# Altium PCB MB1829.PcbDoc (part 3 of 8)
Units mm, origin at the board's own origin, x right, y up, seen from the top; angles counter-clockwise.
Board outline 90 x 110 mm, 6 copper layers (Top Layer, Signal Layer 1, Signal Layer 2, Signal Layer 3, Signal Layer 4, Bottom Layer), stack 1.578 mm thick; 466 components, 354 nets, 2058 pads, 1522 vias.
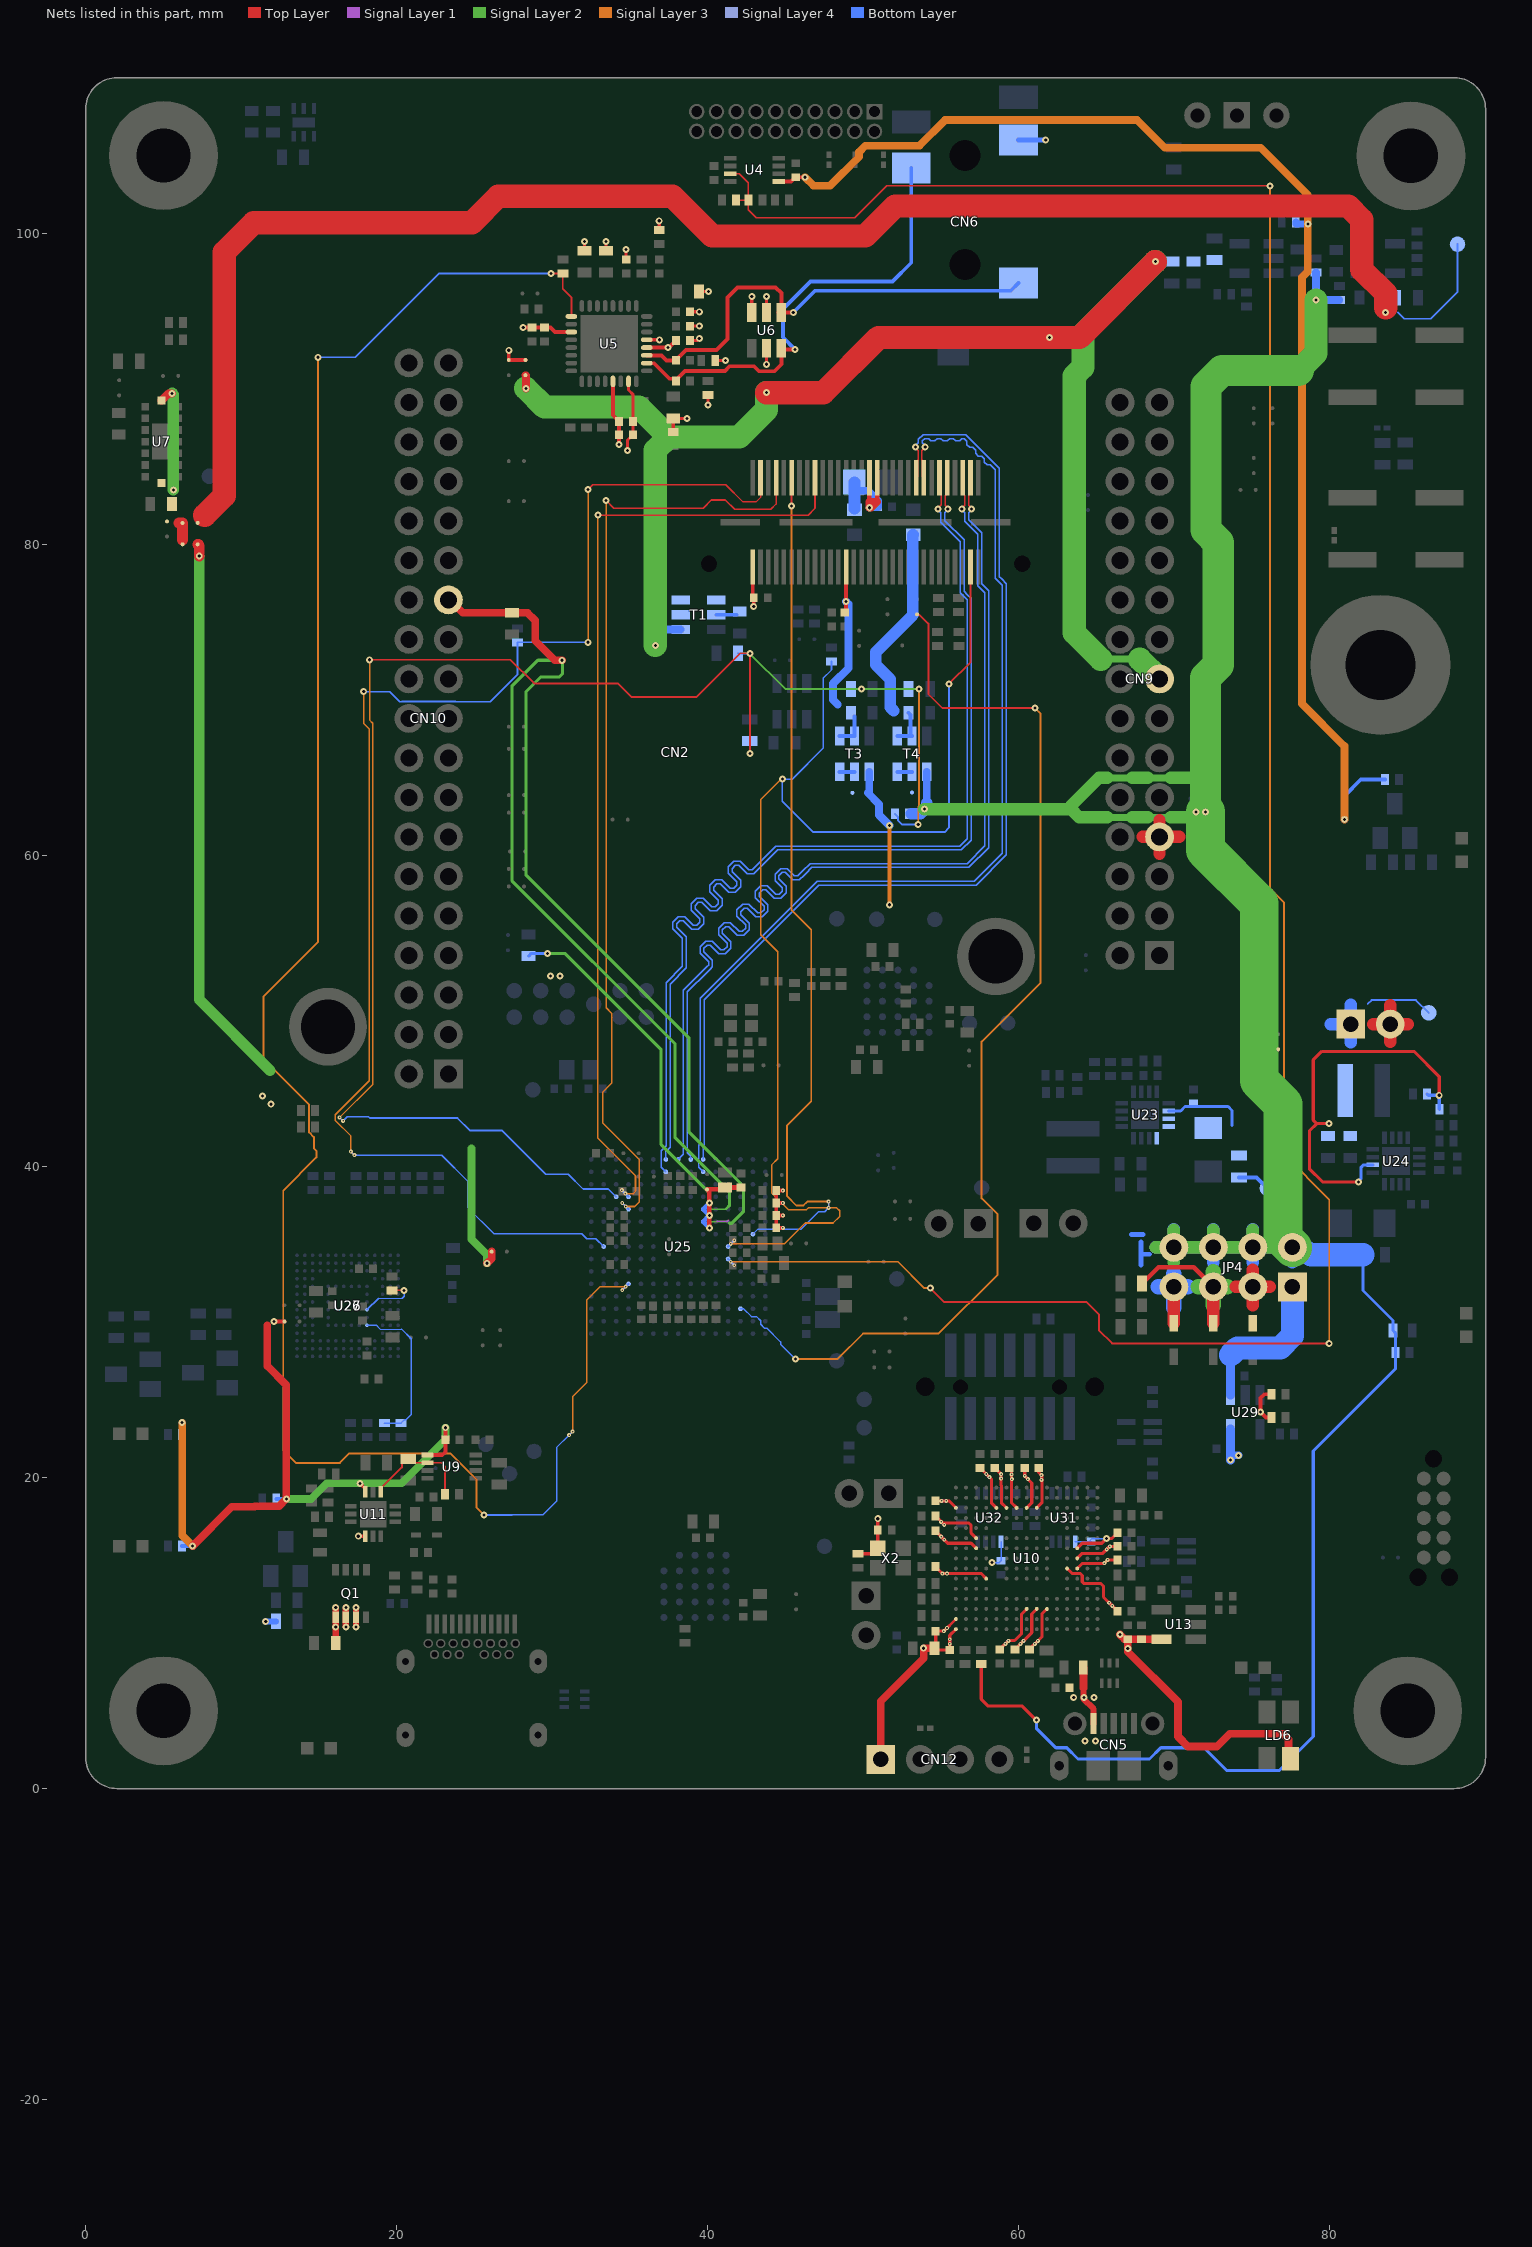
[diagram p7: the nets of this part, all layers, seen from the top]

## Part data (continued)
C119: library part MCD-00199, "Capacitor, Tantalum, 10uF, 16V, 3R, +/-10%, Type_A (3216 metric), T=1.6mm", Manufacturer=AVX, Manufacturer_Part_Number=TAJA106K016R, Package="3216 (metric)"
C121 C122 C123 C124: library part MCD-01101, "Capacitor, MLCC, 100pF, 50V, X7R, +/-5%, 0603, T=0.33mm", Manufacturer=AVX, Manufacturer_Part_Number=06035C101JAT4A, Package=0603
C126: library part MCD-02628, "Capacitor, MLCC, 3.3nF, 50V, X7R, +/-10%, 0402, T=0.5mm", Manufacturer=YAGEO, Manufacturer_Part_Number=CC0402KRX7R9BB332, Package=0402
C127 C128: library part MCD-01775, "Capacitor, MLCC, 3.3pF, 50V, NPO, +/-0.1pF, 0402, T=0.5mm", Manufacturer=YAGEO, Manufacturer_Part_Number=CC0402BRNPO9BN3R3, Package=0402
C129 C136: library part MCD-02610, "Capacitor, MLCC, 10uF, 25V, X5R, +/-10%, 1206, T=1.6mm", Manufacturer=YAGEO, Manufacturer_Part_Number=CC1206KKX5R8BB106, Package=1206
C131 C132 C133 C134: library part MCD-02607, "Capacitor, MLCC, 22uF, 10V, X5R, +/-20%, 0603, T=0.8mm", Manufacturer=YAGEO, Manufacturer_Part_Number=CC0603MRX5R6BB226, Package=0603
C147: library part MCD-00724, "Capacitor, MLCC, 470pF, 50V, NPO, +/-5%, 0402, T=0.5mm", Manufacturer=YAGEO, Manufacturer_Part_Number=CC0402JRNPO9BN471, Package=0402
C149: library part MCD-03051, "Capacitor, MLCC, 22nF, 50V, X7R, +/-10%, 0402, T=0.5mm", Manufacturer=YAGEO, Manufacturer_Part_Number=CC0402KRX7R9BB332, Package=0402
CN1: library part MCD-00147, "Socket, 10x2, 1.27mm, VR, TH, T=4.30mm/2.40mm", Manufacturer="AMPHENOL ICC", Manufacturer_Part_Number=20021311-00020T4LF
CN2: library part MCD-02128, "Socket, 30x2, 0.5mm, VR, SMD, T=3.05mm", Manufacturer=SAMTEC, Manufacturer_Part_Number=QSH-030-01-F-D-A
CN3: library part MCD-00031, "Header_Plug-of-nails, 5x2, 1.27mm, No legs", Manufacturer=TAG-CONNECTLLC, Manufacturer_Part_Number=TC2050-IDC-NL-FP
CN4: library part MCD-01108, "USB_TypeC, SMD+DIP, T= 2.96mm (for 1.6mm pcb)", Manufacturer="CHANT SINCERE (COXOC)", Manufacturer_Part_Number=317JD24BZTF3K3C3
CN5: library part MCD-00028, "MicroUSB_TypeB, 5pins, 0.65mm, RA, SMD, T=2.9mm", Manufacturer=MOLEX, Manufacturer_Part_Number=1050170001
CN6: library part MCD-00263, "Jack_ Socket-Stereo, 3.5mm, 4 pins, RA, SMD, T=5mm", Manufacturer=QIAOD, Manufacturer_Part_Number=PJ3028B-3_4P
CN9: library part MCD-02943, "Socket, 15x2, 2.54mm, VR, TH, T=8.51mm/2.64mm", Manufacturer=SAMTEC, Manufacturer_Part_Number=SSW-115-21-F-D
CN10: library part MCD-02944, "Socket, 19x2, 2.54mm, VR, TH, T=8.51mm/2.64mm", Manufacturer=SAMTEC, Manufacturer_Part_Number=SSW-119-21-F-D
CN11: library part MCD-02021, "Header_MIPI10, 5x2, 1.27mm, VR, SMD, T=6.1mm", Manufacturer=SAMTEC, Manufacturer_Part_Number=FTSH-105-01-L-DV-K-P-TR
CN12: library part MCD-00029, "Header, 4x1, 2.54mm, VR, TH, T=5.84mm/2.54mm", Manufacturer=SAMTEC, Manufacturer_Part_Number=TSW-104-07-G-S
D1 D2 D3: library part MCD-00034, Manufacturer=STMICROELECTRONICS, Manufacturer_HQ_COO=EU
D4: library part MCD-01677, "Small signal Schottky diodes", Manufacturer=STMICROELECTRONICS, Manufacturer_HQ_COO=EU, Manufacturer_Part_Number=BAT54KFILM, Package=SOD-523
H1 H2 H6 H7: library part MCD-02916, "Position hole,  C7D3R5 with 12mm M3 pillar on bottom", Manufacturer=N/A
H3: library part MCD-01612, "POSITION HOLE C9D4R5", Manufacturer=N/A
H4 H5: library part MCD-02915, "Position Hole C5D3R5: with no pillar in 3D, with pad design = c500h350m510.", Manufacturer=N/A
HW1: library part MCD-02189, "Sticker product 25x5 mm", Manufacturer=N/A
HW2: library part MCD-00234, "Sticker ES 6x6 mm", Manufacturer=N/A
HW3: library part MCD-00235, "Sticker Board 25x9 mm", Manufacturer=N/A
JP1 JP2 JP3: library part MCD-00683, "Header, 2x1, 2.54mm, VR, TH, T=5.84mm/2.54mm", Manufacturer=SAMTEC, Manufacturer_Part_Number=TSW-102-07-G-S
JP4: library part MCD-00686, "Header, 4x2, 2.54mm, VR, TH, T=5.84mm/2.54mm", Manufacturer=SAMTEC, Manufacturer_Part_Number=TSW-104-07-G-D
JP5: library part MCD-01904, "Header, 2x1, 2.54mm, VR, TH, T=5.84mm/2.54mm", Manufacturer=SAMTEC, Manufacturer_Part_Number=TSW-102-07-G-S
JP6: library part MCD-00045, "Header, 2x1, 2.54mm, VR, TH, T=5.84mm/2.54mm", Manufacturer=SAMTEC, Manufacturer_Part_Number=TSW-102-07-G-S
L1 L2: library part MCD-01986, "Ferrite bead, 470R @ 100MHz, +/-25%, 200mA, 0R6, 0402, T=0.55mm", Manufacturer=MURATA, Manufacturer_Part_Number=BLM15BD471SN1D, Package=0402
L3: library part MCD-00305, "Ferrite bead, 26R @ 100Mhz, +/-25%, 6000mA, 0R007, 0603, T=0.75mm", Manufacturer=MURATA, Manufacturer_Part_Number=BLM18KG260TN1, Package=0603
L4 L5: library part MCD-00047, "Ferrite bead, 600R @1 00MHz, +/-25%, 350mA, 0R5, 0603, T=0.8mm", Manufacturer=TAI-TECH, Manufacturer_Part_Number=FCM1608KF-601T03, Package=0603
L6: library part MCD-02582, "Inductor, 2.2uH, +/-20%, 8.9A, 0R022, 4x4mm, T=2.1mm", Manufacturer=COILCRAFT, Manufacturer_Part_Number=XGL4020-222MED
L7: library part MCD-02581, "Inductor, 3.3uH, +/-20%, 6.6A, 0R034, 4x4mm, T=2.1mm", Manufacturer=COILCRAFT, Manufacturer_Part_Number=XGL4020-332MED
L8: library part MCD-01060, "Inductor, 2.2uH, +/-20%, 0.7A, 0R156, 0805, T=0.9mm", Manufacturer=MURATA, Manufacturer_Part_Number=LQM21PN2R2MGH, Package=0805
LD1 LD2 LD3 LD7: library part MCD-00588, "LED Green, 0603 SMD, Forward Voltage Typ=2V, Max=2.5V", Manufacturer="OSRAM OPTO SEMICONDUCTORS", Manufacturer_Part_Number="LG Q396-PS-35", Package="LED 0603"
LD4 LD5: library part MCD-00586, "LED Red, 0603 SMD, Forward Voltage Typ=2V, Max=2.5V", Manufacturer="OSRAM OPTO SEMICONDUCTORS", Manufacturer_Part_Number="LS Q976-NR-1", Package="LED 0603"
LD6: library part MCD-02631, "LED Bicolor, Green/Red, 2V, 20mA,  4-PLCC", Manufacturer="WURTH ELEKTRONIK", Manufacturer_Part_Number=150141SV73110, Package=4-PLCC
Q1: library part MCD-01810, "N-channel 30 V, 6 mΩ typ, 11 A STripFET™ H6, Power MOSFET in a PowerFLAT™ 3.3x3.3 package", Manufacturer=STMICROELECTRONICS, Manufacturer_HQ_COO=EU, Package="PowerFLAT 3.3x3.3"
Q2 Q3 Q4 Q5: library part MCD-00073, "NPN Bipolar Transistor", Manufacturer="ON SEMICONDUCTOR", Manufacturer_Part_Number=BSR14, Package=SOT23
R1 R3 R5 R12 R20 R21 R25 R45 R48 R49 R52 R71 R72 R112 R113 R114 R115: library part MCD-00053, "Resistor, 10K, 0402, +/-1%, 1/16W", Manufacturer=YAGEO, Manufacturer_Part_Number=RC0402FR-0710KL, Package=0402
R2 R15 R16 R17 R18 R19 R22 R23 R24 R26 R27 R41 R57 R61 R63 R81 R85 R89 R93 R111 R121 R122: library part MCD-00052, "Resistor, 0R, 0402, +/-5%, 1/16W", Manufacturer=YAGEO, Manufacturer_Part_Number=RC0402JR-070RL, Package=0402
R4: library part MCD-00059, "Resistor, 100K, 0402, +/-1%, 1/16W", Manufacturer=YAGEO, Manufacturer_Part_Number=RC0402FR-0710KL, Package=0402
R6: library part MCD-00057, "Resistor, 2K2, 0402, +/-1%, 1/16W", Manufacturer=YAGEO, Manufacturer_Part_Number=RC0402FR-072K2L, Package=0402
R7 R8 R13 R14 R28 R29: library part MCD-00409, "Resistor, 1K8, 0402, +/-1%, 1/16W", Manufacturer=YAGEO, Manufacturer_Part_Number=RC0402FR-071K8L, Package=0402
R9 R56: library part MCD-00220, "Resistor, 10K, 0603, +/-1%, 1/10W", Alternate_Manufacturer=N/A, Manufacturer=YAGEO, Manufacturer_Part_Number=RC0603FR-0710KL, Package=0603
R10 R11: library part MCD-00485, "Resistor, 51R, 0402, +/-1%, 1/16W", Manufacturer=YAGEO, Manufacturer_Part_Number=RC0402FR-0751RL, Package=0402
R30 R95 R96 R97 R98 R99 R100 R101 R102: library part MCD-00063, "Resistor, 47K, 0402, +/-1%, 1/16W", Manufacturer=YAGEO, Manufacturer_Part_Number=RC0402FR-0747KL, Package=0402
R31: library part MCD-00458, "Resistor, 330K, 0603, +/-1%, 1/10W", Manufacturer=YAGEO, Manufacturer_Part_Number=RC0603FR-07330KL, Package=0603
R32: library part MCD-00444, "Resistor, 27K, 0603, +/-1%, 1/10W", Manufacturer=YAGEO, Manufacturer_Part_Number=RC0603FR-0727KL, Package=0603
R33 R86 R88 R119: library part MCD-00059, "Resistor, 100K, 0402, +/-1%, 1/16W", Manufacturer=YAGEO, Manufacturer_Part_Number=RC0402FR-07100KL, Package=0402
R34 R87 R130: library part MCD-00061, "Resistor, 1K, 0402, +/-1%,1/16W", Manufacturer=YAGEO, Manufacturer_Part_Number=RC0402FR-071KL, Package=0402
R35 R37 R79 R105 R107 R129: library part MCD-00222, "Resistor, 47K, 0603, 1%, 1/10W", Manufacturer=YAGEO, Manufacturer_Part_Number=RC0603FR-0747KL, Package=0603
R36 R55: library part MCD-00220, "Resistor, 10K, 0603, +/-1%, 1/10W", Manufacturer=YAGEO, Manufacturer_Part_Number=RC0603FR-0710KL, Package=0603
R38 R39: library part MCD-02455, "Resistor, 3K9, 0402, +/-1%, 1/16W, +/-100ppm/°C", Manufacturer=YAGEO, Manufacturer_Part_Number=RC0402FR-073K9L, Package=0402
R40 R43: library part MCD-00373, "Resistor, 1K2, 0402, +/-1%, 1/16W", Manufacturer=YAGEO, Manufacturer_Part_Number=RC0402FR-071K2L, Package=0402
R42 R44 R108 R123: library part MCD-00067, "Resistor, 100R, 0402, +/- 1%, 1/16W", Manufacturer=YAGEO, Manufacturer_Part_Number=RC0402FR-07100RL, Package=0402
R46: library part MCD-00185, "Resistor, 3K, 0402, +/-1%, 1/16W", Manufacturer=YAGEO, Manufacturer_Part_Number=RC0402FR-073KL, Package=0402
R47: library part MCD-00433, "Resistor, 2K4, 0402, +/-1%, 1/16W", Manufacturer=YAGEO, Manufacturer_Part_Number=RC0402FR-072K4L, Package=0402
R50 R51 R53: library part MCD-00065, "Resistor, 4K7, 0402, +/-1%, 1/16W", Manufacturer=YAGEO, Manufacturer_Part_Number=RC0402FR-074K7L, Package=0402
R54: library part MCD-00055, "Resistor, 2K7, 0402, +/-1%, 1/16W", Manufacturer=YAGEO, Manufacturer_Part_Number=RC0402FR-072K7L, Package=0402
R58 R64: library part MCD-00405, "Resistor, 160K, 0402, +/-1%, 1/16W", Manufacturer=YAGEO, Manufacturer_Part_Number=RC0402FR-07160KL, Package=0402
R59 R62 R66 R92 R103: library part MCD-00181, "Resistor, 0R, 0603, +/- 0.5mR, 1/4W", Manufacturer=ROHM, Manufacturer_Part_Number=PMR03EZPJ000, Package=0603
R60: library part MCD-00164, "Resistor, 220K, 0402, +/-1%, 1/16W", Manufacturer=YAGEO, Manufacturer_Part_Number=RC0402FR-07220KL, Package=0402
R65: library part MCD-00531, "Resistor, 82K, 0402, +/-1%, 1/16W", Manufacturer=YAGEO, Manufacturer_Part_Number=RC0402FR-0782KL, Package=0402
R67: library part MCD-00430, "Resistor, 22K, 0603, +/-1%, 1/10W", Manufacturer=YAGEO, Manufacturer_Part_Number=RC0603FR-0720KL, Package=0603
R68: library part MCD-00056, "Resistor, 0R, 0603, +/-5%, 1/10W", Manufacturer=YAGEO, Manufacturer_Part_Number=RC0603FR-07200RL, Package=0603
R69 R70: library part MCD-00184, "Resistor, 3K3, 0402, +/-1%, 1/16W", Manufacturer=YAGEO, Manufacturer_Part_Number=RC0402FR-073K3L, Package=0402
R73 R74 R75 R76: library part MCD-00056, "Resistor, 0R, 0603, +/-5%, 1/10W", Manufacturer=YAGEO, Manufacturer_Part_Number=RC0603JR-070RL, Package=0603
R77 R116 R120 R125: library part MCD-00441, "Resistor, 270R, 0402, +/-1%, 1/16W", Manufacturer=YAGEO, Manufacturer_Part_Number=RC0402FR-07270RL, Package=0402
R78: library part MCD-00495, "Resistor, 560K, 0402, +/-1%, 1/16W", Manufacturer=YAGEO, Manufacturer_Part_Number=RC0402FR-07100KL, Package=0402
R80 R104 R106: library part MCD-00223, "Resistor, 100K, 0603, +/- 1%, 1/10W", Manufacturer=YAGEO, Manufacturer_Part_Number=RC0603FR-07100KL, Package=0603
R82 R91: library part MCD-02570, "Resistor, 15K, 0402, +/-0.1%, 1/16W, +/-25ppm/°C", Manufacturer=YAGEO, Manufacturer_Part_Number=RT0402BRD0715KL, Package=0402
R83: library part MCD-02568, "Resistor, 6K8, 0402, +/-0.1%, 1/16W, +/-25ppm/°C", Manufacturer=YAGEO, Manufacturer_Part_Number=RT0402BRD076K8L, Package=0402
R84: library part MCD-02567, "Resistor, 12K, 0402, +/-0.1%, 1/16W, +/-25ppm/°C", Manufacturer=YAGEO, Manufacturer_Part_Number=RT0402BRD0712KL, Package=0402
R90: library part MCD-02550, "Resistor, 47K, 0402, +/-0.1%, 1/16W, +/-25ppm/°C", Manufacturer=YAGEO, Manufacturer_Part_Number=RT0402BRD0747KL, Package=0402
R109: library part MCD-00499, "Resistor, 620R, 0402, +/-1%, 1/16W", Manufacturer=YAGEO, Manufacturer_Part_Number=RC0402FR-07620RL, Package=0402
R110 R117 R118 R124 R126 R127: library part MCD-00481, "Resistor, 47R, 0402, +/-1%, 1/16W", Manufacturer=YAGEO, Manufacturer_Part_Number=RC0402FR-0747RL, Package=0402
R128: library part MCD-00430, "Resistor, 22K, 0603, +/-1%, 1/10W", Manufacturer=YAGEO, Manufacturer_Part_Number=RC0603FR-0722KL, Package=0603
R131: library part MCD-00062, "Resistor, 330R, 0402, +/-1%, 1/16W", Manufacturer=YAGEO, Manufacturer_Part_Number=RC0402FR-07330RL, Package=0402
SB1 SB2 SB3 SB10 SB11 SB12 SB13 SB14 SB15 SB16 SB17 SB18 SB19 SB22 SB25 SB28 SB34 SB35 SB38 SB39 SB40 SB43 SB46: library part MCD-02162, "Solder Bridge 0402 OFF", Manufacturer=YAGEO, Manufacturer_Part_Number=RC0402JR-070RL, Package=SB0402
SB4 SB5 SB6 SB9 SB20 SB21 SB23 SB24 SB26 SB27 SB29 SB30 SB31 SB32 SB33 SB36 SB37 SB41 SB42 SB44 SB45 SB47 SB48 SB49 SB50 SB51 SB52 SB53 SB54 SB55 SB56 SB57 SB58 SB59 SB60 SB61: library part MCD-01618, "Solder Bridge 0402 ON", Manufacturer=YAGEO, Manufacturer_Part_Number=RC0402JR-070RL, Package=SB0402
SB7 SB8: library part MCD-02162, "Solder Bridge 0402 OFF", Alternate_Manufacturer=N/A, Manufacturer=YAGEO, Manufacturer_Part_Number=RC0402JR-070RL, Package=SB0402
SW1: library part MCD-00566, "Mechanical Slide Switches 1K2 BLK ACT GOLD STRT MNT", Manufacturer=EAO, Manufacturer_Part_Number=09.03290.01
T1 T2 T3: library part MCD-01926, "20 V, P-channel Trench MOSFET", Manufacturer=NEXPERIA, Manufacturer_Part_Number=PMN30XPX, Package=TSOP6
T4: library part MCD-03170, "20 V, P-channel Trench MOSFET", Manufacturer=NEXPERIA, Manufacturer_Part_Number=PMN30XPX, Package=TSOP6
TP1 TP2 TP4 TP5 TP6 TP7 TP8 TP9 TP10 TP11 TP12 TP13 TP14 TP15 TP16 TP17 TP18 TP19 TP20 TP21 TP22 TP23 TP24 TP25 TP26 TP27 TP28 TP29 TP30 TP31: library part MCD-00074, "Test Point 1mm", Manufacturer=N/A
TP3: library part MCD-00074, "Test Point 1mm", Manufacturer=N/A, Manufacturer_Part_Number=n/a
U1 U2 U3 U8 U16 U17 U21: library part MCD-00170, "ESD protection 6V1", Manufacturer=STMICROELECTRONICS, Manufacturer_HQ_COO=EU, Manufacturer_Part_Number=ESDALC6V1-1U2
U4 U9 U31 U32: library part MCD-00264, "Dual bit dual supply bus transceiver", Manufacturer="TEXAS INSTRUMENTS"
U5: library part MCD-00265, "Low-Power, Stereo Codec with Headphone Amp", Manufacturer="CIRRUS LOGIC"
U6: library part MCD-00247, "Quad Bidir ESD protection", Manufacturer=STMICROELECTRONICS, Manufacturer_HQ_COO=EU
U7: library part MCD-02590, "Time-of-Flight 8x8 multizone ranging sensor with wide field of view", Manufacturer=STMICROELECTRONICS, Package="Optical LGA16"
U10: library part MCD-00596, "STM32F723IEK  (STM32F7) BGA176", Manufacturer=STMICROELECTRONICS, Manufacturer_HQ_COO=EU, Manufacturer_Part_Number=STM32F723IEK6
U11: library part MCD-01809, "USB Type-C Port Protection for USB Power Delivery, PPS compliant", Manufacturer=STMICROELECTRONICS, Manufacturer_HQ_COO=EU, Package=QFN-12L
U12: library part MCD-01207, "High power Transient voltage suppressor:25V/35A EOS and ESD transients protection.", Manufacturer=STMICROELECTRONICS, Manufacturer_HQ_COO=EU, Manufacturer_Part_Number=ESDA25P35-1U1M, Package=QFN1610
U13: library part MCD-00086, "Ultra low drop-low noise BiCMOS voltage, regulators low ESR capacitors compatible", Manufacturer=STMICROELECTRONICS, Manufacturer_HQ_COO=EU
U14 U35: library part MCD-00649, "Common mode filter with ESD protection for USB 2.0 interface", Manufacturer=STMICROELECTRONICS, Manufacturer_HQ_COO=EU
U15 U28: library part MCD-01026, "High power transient voltage suppressor", Manufacturer=STMICROELECTRONICS, Manufacturer_HQ_COO=EU, Manufacturer_Part_Number=ESDA7P120-1U1M, Package=QFN1610
U18: library part MCD-02159, "temperature sensor", Alternate_Manufacturer=N/A, Manufacturer=STMICROELECTRONICS, Manufacturer_HQ_COO=EU, Package="UDFN 6-pins 2x2x0.5mm"
U19 U20: library part MCD-02175, "LDO VOLTAGE REGULATOR, Adjustable, 150mA,", Manufacturer="TEXAS INSTRUMENTS", Manufacturer_Part_Number=TPS76301DBVT, Package=SOT23-5
U22: library part MCD-02166, "Memory,Octo-SPI-NOR,512Mb,x1/x8,133/200MHz,1.8V,DTR,BGA24, CMOS MXSMIO", Manufacturer=MACRONIX, Manufacturer_Part_Number=MX25UM51245GXDI00, Package=BGA24
U23 U24: library part MCD-02580, "Buck converter, 2A, 3V to 17V input, Fsw 1.25/2.5 MHz, 3x3 VQFN16", Manufacturer="TEXAS INSTRUMENTS"
U25: library part MCD-03270, "MCU, ARM Cortex-M33, 4MB Flash, 2.5MB RAM, With Crypto", Manufacturer=STMICROELECTRONICS, Manufacturer_HQ_COO=EU, Manufacturer_Part_Number=STM32U599NJH6Q, Package=TFBGA216
U26: library part MCD-01137, "4G MultiMediaCard (MMC) controller and NAND Flash", Manufacturer=MICRON, Package=FBGA153
U27: library part MCD-02799, "Memory, eMMC, 4GB, 15nm ,WFBGA , 153 pins", Manufacturer=KIOXIA, Manufacturer_Part_Number=THGBMTG5D1LBAIL, Package=WFBGA153
U29: library part MCD-00159, "500mA, Enhanced single channel power switches with active high enable pin", Manufacturer=STMICROELECTRONICS, Manufacturer_HQ_COO=EU
U30 U33: library part MCD-00136, "Dual Transil array for ESD protection", Manufacturer=STMICROELECTRONICS, Manufacturer_HQ_COO=EU
U34: library part MCD-02904, "Memory,Hexa-SPI-PSRAM,512Mb,x8x16,200MHz,1.8V,DDR,BGA24, PASR LVCMOS", Manufacturer="AP MEMORY TECHNOLOGY CORP.", Manufacturer_Part_Number=APS512XXN-OBR-BG, Package=BGA24
X1: library part MCD-01476, "Crystal, 16 MHz, 8pF, +/-20ppm, 200R, 2x1.6mm", Manufacturer=NDK, Manufacturer_Part_Number=NX2016SA-16MHZ-EXS00A-CS07826, Package=2x1.6mm
X2: library part MCD-00597, "Oscillator, SPXO, 25Mhz, +/-50ppm, 3V3, square wave, 2.5x2mm", Manufacturer=NDK, Manufacturer_Part_Number=NZ2520SH-25MHZ-END4869C, Package=2.5x2mm
X3: library part MCD-01479, "Crystal, 32.768kHz, 6pF, +/-20ppm, 80K, 2.05x1.2mm", Manufacturer=NDK, Manufacturer_Part_Number=NX2012SA-32.768KHZ-EXS00A-MU00527, Package=2.05x1.2mm

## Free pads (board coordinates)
  round 0.508 on Mech16: 1(22.966,-25.136) 1(71.839,-25.188)

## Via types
v1: diameter 0.45, hole 0.2, Top Layer to Bottom Layer, tented both sides, 1062 vias
v2: diameter 0.25, hole 0.1, Signal Layer 4 to Bottom Layer, tented both sides, 274 vias
v3: diameter 0.25, hole 0.1, Signal Layer 3 to Signal Layer 4, tented both sides, 119 vias
v4: diameter 0.25, hole 0.1, Top Layer to Signal Layer 1, tented both sides, 47 vias
v5: diameter 0.25, hole 0.1, Signal Layer 1 to Signal Layer 2, tented both sides, 20 vias

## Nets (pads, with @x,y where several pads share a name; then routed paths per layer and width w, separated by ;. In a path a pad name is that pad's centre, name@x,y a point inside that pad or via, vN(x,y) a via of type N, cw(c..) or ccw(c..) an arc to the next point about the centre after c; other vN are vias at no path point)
1V8: C117.2 CN9.15 R59.2 R62.2 SB2.1 SB49.1 T1.4 TP2.1 | length 98.2
  Top Layer w0.2: 62.475,93.3 62.5,93.325
  Top Layer w0.5: SB2.1@28.275,90.875 28.3,90.85 v1(28.3,90.025)
  Top Layer w1.5: v1(43.775,89.75) 47.425,89.75 50.975,93.3 v1(61.959,93.3) 62.475,93.3 63.9,93.3 v1(68.775,98.175)
  Signal Layer 2 w0.45: 65.725,72.614 67.775,72.614
  Signal Layer 2 w1.5: v1(28.3,90.025) 29.5,88.825 35.551,88.825 37.475,86.901 ; v1(36.625,73.5) 36.625,86.051 37.475,86.901 ; v1(43.775,89.75) 43.775,88.65 42.026,86.901 37.475,86.901 ; 65.257,72.616 63.55,74.324 63.55,90.825 64.115,91.39 64.115,93.515 v1(68.775,98.175) ; 67.775,72.625 67.775,72.609 CN9.15@69.04,71.344 CN9.15@68.973,71.411
  Bottom Layer w0.25: v1(61.959,93.3) TP2.1@63.394,93.3
  Bottom Layer w0.5: v1(36.625,73.5) SB49.1@36.625,74.521 T1.4@38.25,74.521
1V8_AUDIO: C11.2 C12.2 C13.2 C19.2 C20.2 SB2.2 SB3.2 U5.5 U5.12 U5.27 | length 11.2
  Top Layer w0.25: v1(27.2,92.475) SB3.2@27.2,91.85 SB2.2@28.275,91.85 ; v1(28.129,93.941) 28.141,93.941 28.15,93.95 C11.2@28.7,93.95 ; C11.2@28.7,93.95 C12.2@29.5,93.95 ; C12.2@29.5,93.941 29.885,93.941 30.175,93.65 U5.27@31.225,93.65 ; U5.5@33.9,90.475 33.9,88.3 C19.2@34.3,87.9 C20.2@34.3,87.05 v1(34.3,86.425) ; U5.12@36.075,92.65 37.5,92.65 C13.2@37.95,93.1
  other v1: 37.439,92.65
1V8_LCD: C22.2 C121.2 CN2.60 SB49.2 T1.1 T1.2 T1.5 T1.6 | length 3.6
  Top Layer w0.25: C22.2@42.885,76.636 CN2.60@42.885,78.357 ; v1(42.95,75.996) C22.2@42.95,76.571
  Bottom Layer w0.25: T1.2@40.55,75.471 C121.2@41.85,75.471
2V8: C118.2 R66.2 SB13.1 TP1.1 | length 108.3
  Top Layer w1.5: 7.65,81.875 8.9,83.125 8.9,98.77 10.805,100.675 24.835,100.675 26.535,102.375 37.725,102.375 40.275,99.825 50.125,99.825 52.05,101.75 81.171,101.75 82.05,100.871 82.05,97.656 83.575,96.131 83.575,95.2
  Bottom Layer w0.12: 84.382,94.9 84.782,94.5 86.475,94.5 88.2,96.225 TP1.1@88.2,99.3
  other v1: 83.571,94.9
3V3: C1.2 C71.2 CN9.7 JP1.2 R57.1 R77.2 R116.2 R120.2 R125.2 SB37.1 SB41.1 SB53.1 SB60.1 T3.4 U4.1 U9.1 U11.12 | length 193.8
  Top Layer w0.25: v1(12.1,30.025) SB41.1@12.775,30.025 ; v1(17.625,19.625) 17.975,19.275 U11.12@17.975,19.075 ; U9.1@21.975,21.45 22.925,21.45 23.125,21.65 C71.2@23.125,22.425 v1(23.125,23.2) ; U4.1@44.55,103.325 45.35,103.325 45.625,103.6 C1.2@45.65,103.6 v1(46.25,103.6)
  Top Layer w0.5: v1(6.875,15.6) 9.4,18.125 10.863,18.125 10.888,18.15 12.425,18.15 v1(12.9,18.625) 12.9,25.95 11.675,27.175 11.675,29.775 ; v1(25.8,33.775) 26.1,34.075 SB37.1@26.1,34.525
  Top Layer w0.7: SB60.1@7.2,80 7.25,80 7.25,79.925 7.3,79.875 v1(7.3,79.25)
  Top Layer w0.8: 67.95,61.184 CN9.7@69.04,61.184 ; 69.04,60.1 CN9.7@69.04,61.184 ; 69.04,62.275 CN9.7@69.04,61.184 ; 70.296,61.184 CN9.7@69.04,61.184 ; 82.775,49.15 JP1.2@83.87,49.15 ; 83.87,48.03 JP1.2@83.87,49.15 ; 83.87,50.366 JP1.2@83.87,49.15 ; 85,49.15 JP1.2@83.87,49.15
  Signal Layer 2 w0.5: v1(12.9,18.625) 14.5,18.625 15.5,19.625 v1(17.625,19.625) 20.325,19.625 23.125,22.425 v1(23.125,23.2) ; 24.8,41.15 24.8,35.325 25.8,34.325 v1(25.8,33.775)
  Signal Layer 2 w0.7: v1(7.3,79.25) 7.3,50.725 11.85,46.175
  Signal Layer 3 w0.25: v1(51.675,56.825) v1(51.675,61.925)
  Signal Layer 3 w0.5: v1(6.2,23.525) 6.2,16.275 v1(6.875,15.6) ; v1(46.25,103.6) 46.8,103.05 47.85,103.05 49.725,104.925 49.725,105.225 50.125,105.625 53.6,105.625 55.25,107.275 67.598,107.275 69.375,105.498 75.552,105.498 78.575,102.475 v1(78.575,100.6) 78.575,97.541 78.2,97.166 78.2,69.75 80.925,67.025 v1(80.925,62.3)
  Bottom Layer w0.25: R125.2@6.2,15.6 v1(6.875,15.6) ; R116.2@6.2,22.775 v1(6.2,23.525) ; R120.2@12.25,18.625 v1(12.9,18.625) ; v1(80.925,62.3) 80.925,63.825 81.979,64.879 R77.2@83.546,64.879
  Bottom Layer w0.45: R57.1@77.8,100.725 77.8,100.63 77.83,100.6 v1(78.575,100.6)
  Bottom Layer w0.5: T3.4@50.375,65.371 50.375,64.121 SB53.1@50.275,64.021 51.006,63.291 51.006,62.594 v1(51.675,61.925)
  other v1: 11.925,44 11.375,44.525 29.875,52.25 30.5,52.25
3V3_LCD: C24.2 C123.2 CN2.36 SB53.2 T3.1 T3.2 T3.5 T3.6 | length 13.4
  Top Layer w0.25: C24.2@48.8,75.621 48.885,75.706 v1(48.885,76.321) 48.885,78.536 CN2.36@48.889,78.54
  Bottom Layer w0.25: T3.6@48.475,65.371 T3.5@49.425,65.371 ; T3.1@48.475,67.671 T3.2@49.425,67.671 C123.2@49.425,68.946
  Bottom Layer w0.5: 48.35,69.7 48.05,70 48.05,71.046 49.05,72.046 49.05,76.156 v1(48.885,76.321)
3V3_SMPS: C131.1 C132.2 JP1.1 L6.2 R88.2 R89.2 TP13.1 U24.14 | length 33.4
  Top Layer w0.2: v1(79.929,42.752) 79.152,42.752 ; v1(81.825,39) 79.525,39 78.675,39.85 78.675,42.275 79.152,42.752 ; v1(87.025,44.575) 87.025,45.775 85.4,47.4 79.475,47.4 78.925,46.85 78.925,42.979 79.152,42.752
  Bottom Layer w0.12: 82.425,50.45 82.675,50.7 85.525,50.7 TP13.1@86.35,49.875
  Bottom Layer w0.2: v1(81.825,39) 81.825,39.067 82,39.242 82,39.95 82.15,40.1 U24.14@82.75,40.1 ; R88.2@86.25,44.65 86.325,44.575 v1(87.025,44.575) 87.025,43.7 R89.2@87.05,43.675
  Bottom Layer w0.8: 80.034,49.15 JP1.1@81.33,49.15 ; 81.33,47.97 JP1.1@81.33,49.15 ; 81.33,50.395 JP1.1@81.33,49.15
3V3_STLK: C73.1 C74.1 C75.1 C76.1 C77.1 C80.1 C83.1 C85.1 C86.1 C87.1 C89.1 C91.1 C92.1 C101.1 C102.2 C103.2 C104.1 C106.2 C107.1 C108.1 C109.1 C111.2 C145.2 C146.2 CN12.1 LD6.4 R45.1 U10.C1 U10.C5 U10.C6 U10.C7 U10.C8 U10.C9 U10.F3 U10.G3 U10.G13 U10.H13 U10.J12 U10.J13 U10.K4 U10.N8 U10.N9 U10.N10 U10.P1 U10.R1 U13.5 U31.1 U32.1 X2.4 | length 95.9
  Top Layer w0.2: C80.1@54.625,18.5 55.5,18.5 U10.C1@55.95,18.05 ; C92.1@54.65,14.25 v4(55.075,13.825) 57.575,13.825 U10.K4@57.9,13.5 ; C86.1@54.65,16.575 54.65,16.55 55.425,15.775 56.925,15.775 U10.G3@57.25,15.45 ; C83.1@54.65,17.525 v4@55,17.175 ; v4(55,17.15) v4@55,17.175 ; U10.R1@55.95,10.25 55.55,9.85 C111.2@55.55,8.9 54.7,8.9 C106.2@54.575,9.025 54.65,9.1 C104.1@54.65,10.125 v4(55.175,10.125) U10.P1@55.95,10.9 ; U10.F3@57.25,16.1 56.925,16.425 56.925,16.925 56.775,17.075 55.815,17.075 55.1,17.075 v4@55,17.175 ; C75.1@57.5,20.625 58.225,19.9 58.225,18.375 U10.C5@58.55,18.05 ; C76.1@58.45,20.625 v4(58.86,20.215) 58.86,19.5 58.875,19.485 58.875,18.375 ; C107.1@58.775,8.95 59.35,9.525 59.725,9.525 60.175,9.975 60.175,11.225 U10.N8@60.5,11.55 ; 59.013,18.238 58.875,18.375 ; U10.C6@59.2,18.05 58.875,18.375 ; C77.1@59.375,20.625 59.525,20.475 59.525,18.375 U10.C7@59.85,18.05 ; C108.1@59.75,8.95 60.825,10.025 60.825,11.225 U10.N9@61.15,11.55 ; C73.1@60.375,20.625 v4(60.375,20.1) 60.825,19.65 60.825,18.375 U10.C8@60.5,18.05 ; C109.1@60.675,8.95 61.475,9.75 61.475,11.225 U10.N10@61.8,11.55 ; U10.C9@61.15,18.05 61.475,18.375 61.475,20.125 v4(61.45,20.15) 61.275,20.325 C74.1@61.275,20.625 ; U10.J12@63.1,14.15 63.425,13.825 63.95,13.825 64.075,13.7 64.075,13.3 64.2,13.175 65.275,13.175 65.44,13.01 65.44,12.31 v4(66,11.75) C101.1@66.35,11.4 ; U10.J13@63.75,14.15 64.075,14.475 65.475,14.475 v4(65.7,14.7) C91.1@66.35,14.7 ; U10.H13@63.75,14.8 64.075,15.125 65.4,15.125 v4(65.85,15.575) C89.1@66.35,15.575 ; U10.G13@63.75,15.45 64.075,15.775 65.185,15.775 65.325,15.775 v1(65.625,16.075) 65.975,16.075 C87.1@66.35,16.45
  Top Layer w0.25: R45.1@49.65,15.1 50.575,15.1 X2.4@50.925,15.45 ; X2.4@50.925,15.45 C85.1@50.925,16.625 v1(50.925,17.35)
  Top Layer w0.5: CN12.1@51.115,1.875 51.115,5.615 53.875,8.375 v1(53.875,9.025) C106.2@54.575,9.025 ; v1(66.5,9.9) 66.795,9.605 66.995,9.605 C102.2@67,9.6 ; U13.5@69.175,9.6 C103.2@67.875,9.6 C102.2@67,9.6 ; LD6.4@77.45,1.925 77.332,2.043 77.332,3.175 76.977,3.53 73.555,3.53 72.725,2.7 70.871,2.7 70.225,3.346 70.225,5.575 67,8.8 v1(67,9) C102.2@67,9.6
  Signal Layer 1 w0.2: v4(55,16.2) v5(55.2,16) ; v4(55,17.15) v5(55.2,16.95) ; v4(55.025,18.5) v5(55.325,18.5) ; v4(55.075,13.825) v5(55.375,13.825) ; v4(55.175,10.125) v5(55.375,10.325) ; v4(55.55,9.3) v5(55.55,9.6) ; v4(57.9,20.225) v5(58.1,20.025) ; v5@58.86,19.935 v4(58.86,20.215) ; v4(59.125,9.3) v5(59.325,9.5) ; v5@59.525,19.925 v4(59.525,20.2) ; v4(60.1,9.3) v5(60.3,9.5) ; v4(60.375,20.1) v5(60.575,19.9) ; v4(61.025,9.3) v5(61.225,9.5) ; v5(61.45,19.85) v4(61.45,20.15) ; v5(65.5,14.5) v4(65.7,14.7) ; v5(65.65,15.375) v4(65.85,15.575) ; v5(65.8,11.95) v4(66,11.75)
  Bottom Layer w0.1: v1(58.275,14.525) 58.725,14.525 C146.2@58.85,14.65 U32.1@58.85,15.875 ; U31.1@63.625,15.875 C145.2@64.65,15.875 64.575,15.95 64.7,16.075 v1(65.625,16.075)
  other v5: 59.55,19.9 58.85,19.925
5V: JP4.2 JP4.4 JP4.6 JP4.8 R54.1 R61.1 R63.1 R78.2 R92.1 R103.1 R109.2 SB52.1 SB54.1 T4.4 TP23.1 U28.1 | length 205.1
  Top Layer w0.2: R54.1@57.575,8 57.575,5.75 58.025,5.3 60.225,5.3 v1(61.125,4.4)
  Top Layer w0.8: JP4.8@69.95,34.81 JP4.8@69.965,34.795
  Signal Layer 2 w0.4: v1@71.2,62.8 v1(71.375,62.8)
  Signal Layer 2 w0.45: 65.675,62.45 67.275,62.45 ; 65.675,64.99 67.275,64.99 ; 68.275,62.45 69.775,62.45 ; 68.275,64.99 69.775,64.99
  Signal Layer 2 w0.5: JP4.2@77.585,34.795 77.585,35.917
  Signal Layer 2 w0.8: v1(53.925,62.975) 63.35,62.975 ; 65.675,62.45 63.875,62.45 63.35,62.975 ; 65.675,64.99 65.15,64.99 63.35,63.19 63.35,62.975 ; 67.275,62.45 68.275,62.45 ; 67.275,64.99 68.275,64.99 ; 68.8,34.795 JP4.8@69.965,34.795 ; 69.775,62.45 71.025,62.45 v1(71.375,62.8) v1(72,62.8) ; 69.775,64.99 71.025,64.99 ; 69.965,33.825 JP4.8@69.965,34.795 ; 69.965,35.917 JP4.8@69.965,34.795 ; 72.505,35.917 JP4.6@72.505,34.795 ; 75.045,35.917 JP4.4@75.045,34.795 ; JP4.2@77.585,34.795 JP4.4@75.045,34.795 ; JP4.8@69.965,34.795 JP4.6@72.505,34.795 ; JP4.6@72.505,34.795 JP4.4@75.045,34.795
  Signal Layer 2 w1.5: 77.985,91.176 79.1,92.291 v1(79.1,95.7)
  Signal Layer 2 w2: v1(72,62.8) 72,71.425 72.819,72.244 72.819,80.111 72.019,80.912 72.019,90.142 73.053,91.176 77.985,91.176
  Signal Layer 2 w2.5: v1(72,62.8) 72,60.35 75.45,56.9 75.45,45.525 76.975,44 76.975,35.405 JP4.2@77.585,34.795
  Bottom Layer w0.2: v1(61.125,4.4) 61.125,3.877 62.377,2.625 63.075,2.625 63.8,1.9 68.4,1.9 69.125,2.625 71.9,2.625 73.35,1.175 76.75,1.175 78.925,3.35 78.925,21.7 84.2,26.975 R109.2@84.2,28.05 84.2,29.3 U28.1@84.05,29.45 84.05,30.1 82.125,32.025 R103.1@82.125,34.325
  Bottom Layer w0.25: R92.1@74.15,39.3 75.275,39.3 TP23.1@75.975,38.6
  Bottom Layer w0.3: 67.225,35.625 67.975,35.625 ; 67.85,33.65 67.85,34.35 ; 67.85,35.15 67.85,34.35 ; 68.4,34.35 67.85,34.35
  Bottom Layer w0.5: 54.075,63.371 T4.4@54.075,65.371 ; 78.785,34.325 78.855,34.255 ; R61.1@79.1,97.473 v1(79.1,95.7) R63.1@80.6,95.7
  Bottom Layer w0.75: R78.2@53.075,62.675 53.667,62.675 54.075,63.083 54.075,63.371
  Bottom Layer w0.8: 68.78,34.795 JP4.8@69.965,34.795 ; 69.965,35.98 JP4.8@69.965,34.795 ; 72.505,33.825 JP4.6@72.505,34.795 ; 72.505,35.98 JP4.6@72.505,34.795 ; 75.045,33.825 JP4.4@75.045,34.795 ; 75.045,35.98 JP4.4@75.045,34.795 ; 77.585,33.825 JP4.2@77.585,34.795 ; 77.585,35.98 JP4.2@77.585,34.795 ; 78.625,34.795 JP4.2@77.585,34.795 ; JP4.8@69.965,34.795 JP4.6@72.505,34.795 ; JP4.6@72.505,34.795 JP4.4@75.045,34.795 ; JP4.4@75.045,34.795 JP4.2@77.585,34.795
  Bottom Layer w1.5: 78.785,34.325 R103.1@82.125,34.325
5V_LCD: C122.2 L4.1 SB52.2 T4.1 T4.2 T4.5 T4.6 | length 16.3
  Bottom Layer w0.25: T4.6@52.175,65.371 T4.5@53.125,65.371 ; T4.1@52.175,67.671 T4.2@53.125,67.671 53.034,67.763 53.034,69.038 C122.2@52.9,69.171
  Bottom Layer w0.75: 51.948,69.298 51.725,69.521 51.725,71.328 50.8,72.253 50.8,73.071 53.175,75.446 53.175,80.6 L4.1@53.2,80.625
5V_STLK: C141.2 JP4.1 U29.1 | length 10.2
  Bottom Layer w0.6: U29.1@73.6,25.3 C141.2@73.6,26.525 73.6,27.875
  Bottom Layer w1.5: 73.6,27.875 74.05,28.325 76.8,28.325 77.585,29.11 JP4.1@77.585,32.255
5V_UCPD: C105.1 D1.1 JP4.5 Q1.1 Q1.2 Q1.3 R31.2 R129.1 U11.4 | length 17.8
  Top Layer w0.25: v1(17.525,16.225) U11.4@17.975,16.225 ; JP4.5@72.5,32.25 JP4.5@72.505,32.255
  Top Layer w0.3: R31.2@67.925,32.475 68.975,33.525 71.235,33.525 JP4.5@72.505,32.255
  Top Layer w0.4: C105.1@16.075,9.35 v1(16.075,10.4) Q1.1@16.075,11.025 v1(16.075,11.65) ; v1(16.725,10.4) Q1.2@16.725,11.025 v1(16.725,11.65) ; v1(17.375,10.4) Q1.3@17.375,11.025 v1(17.375,11.65)
  Top Layer w0.8: D1.1@72.5,29.92 JP4.5@72.5,32.25
  Signal Layer 2 w1: 71.525,32.255 JP4.5@72.505,32.255 ; 72.505,31.085 JP4.5@72.505,32.255 ; 72.505,33.225 JP4.5@72.505,32.255 ; JP4.5@73.405,32.255 JP4.5@72.505,32.255
  Bottom Layer w0.4: v1(11.575,10.75) R129.1@12.225,10.75
5V_USB_CHGR: C112.2 C142.2 CN5.1 D2.1 JP4.7 R33.2 R34.2 U15.1 U29.5 | length 15.4
  Top Layer w0.25: R34.2@76.25,23.85 75.875,23.85 v1(75.525,24.2) 75.525,25.1 75.775,25.35 R33.2@76.25,25.35
  Top Layer w0.4: 64.15,6.475 64.15,5.775 64.8,5.125 CN5.1@64.8,4.175
  Top Layer w0.5: 64.15,6.475 U15.1@64.15,7.775
  Top Layer w0.8: D2.1@69.95,29.92 JP4.7@69.95,32.24
  Top Layer w1: JP4.7@69.95,32.24 JP4.7@69.965,32.255
  Bottom Layer w0.5: 73.6,21.435 73.61,21.425 v1(74.125,21.425)
  Bottom Layer w0.6: v1(73.6,21.125) 73.6,21.435 C142.2@73.6,21.85 U29.5@73.6,23.1
  Bottom Layer w1: 68.95,32.255 JP4.7@69.965,32.255 ; 69.965,30.925 JP4.7@69.965,32.255 ; JP4.7@69.965,33.1 JP4.7@69.965,32.255 ; JP4.7@70.85,32.255 JP4.7@69.965,32.255
  other v1: 64.255,3.06 64.93,3.06 63.525,5.85 64.175,5.85 64.825,5.85
5V_VIN: D3.1 JP4.3 SB26.1 | length 4.5
  Top Layer w0.8: 73.95,32.255 JP4.3@75.045,32.255 ; 75.045,31.075 JP4.3@75.045,32.255 ; 75.045,33.35 JP4.3@75.045,32.255 ; 76.14,32.255 JP4.3@75.045,32.255
5VIN: C129.2 C130.2 R92.2 U23.10 U23.11 U23.12 U23.13 | length 5.3
  Bottom Layer w0.2: U23.10@69.622,43.564 70.394,43.564 70.68,43.85 73.45,43.85 73.7,43.6 73.7,42.625
A_GND: C3.1 C4.1 C5.1 C7.1 C9.1 C10.1 C13.1 C16.1 C19.1 C20.1 CN6.3 R4.1 R10.1 R11.1 R15.1 U5.7 U5.13 U6.2 U6.3 U6.5 | length 18.3
  Top Layer w0.2: C3.1@32.075,98.875 v1(32.075,99.475) ; C4.1@33.45,98.875 v1(33.45,99.475) ; C5.1@34.75,98.4 v1(34.75,98.95) ; v1(34.825,86.025) 34.825,86.675 C20.1@35.2,87.05 C19.1@35.2,87.9 35.2,89.625 34.9,89.925 U5.7@34.9,90.475 ; U5.13@36.075,93.15 v1(36.9,93.15) ; R4.1@36.875,100.2 v1(36.875,100.8) ; R15.1@37.775,87.225 C16.1@37.775,88.1 v1(38.65,88.1) ; C13.1@38.85,93.1 39.25,93.1 39.333,93.1 39.45,93.217 v1(39.45,93.239) ; C10.1@38.85,94.025 v1(39.45,94.025) ; C9.1@38.85,94.95 v1(39.45,94.95) ; C7.1@39.425,96.25 v1(40.05,96.25) ; v1(40,88.95) R11.1@40,89.6 ; R10.1@40.475,91.825 40.525,91.775 40.575,91.825 v1(41.125,91.825) ; U6.3@42.825,94.9 v1(42.825,95.925) ; v1(43.775,91.575) U6.5@43.775,92.6 ; U6.2@43.775,94.9 v1(43.775,95.925)
  Bottom Layer w0.3: CN6.3@59.975,106 v1(61.725,106)
AGND: C25.1 C37.2 C41.1 C43.1 C45.1 C48.1 C125.1 CN10.25 L1.2 SB30.2 U25.K5 U25.K6 | length 135.5
  Top Layer w0.25: v4(44.825,36.05) C48.1@44.4,36.05 C45.1@44.4,36.85 ; v4(44.825,36.85) C45.1@44.4,36.85 ; v4(44.825,37.65) C43.1@44.4,37.65 ; v4(44.825,38.45) C41.1@44.4,38.45 C43.1@44.4,37.65 ; C45.1@44.4,36.85 C43.1@44.4,37.65
  Top Layer w0.3: v1(40.1,36.05) v1(40.1,36.85) v1(40.1,37.65) 40.1,38.375 SB30.2@39.95,38.525 40.975,38.525 L1.2@41.1,38.65 C37.2@42.125,38.65
  Top Layer w0.5: CN10.25@23.32,76.424 23.412,76.424 24.237,75.6 C25.1@27.4,75.6 28.4,75.6 28.9,75.1 28.9,73.8 30.155,72.545 v1(30.625,72.545)
  Signal Layer 1 w0.1: 40.575,36.475 41.275,36.475 41.325,36.525
  Signal Layer 2 w0.1: 40.1,36.45 41.3,36.45 41.4,36.35 ; 40.1,37.25 41.15,37.25 41.2,37.3
  Signal Layer 2 w0.2: v1(29.7,53.7) 30.8,53.7 37,47.5 37,41.4 40.1,38.3 v1(40.1,37.65) 40.1,37.25 v1(40.1,36.85) 40.1,36.45 v1(40.1,36.05) ; 41.2,37.3 41.4,37.5 41.4,38.336 37.9,41.836 37.9,47.873 27.4,58.373 27.4,70.875 29.07,72.545 v1(30.625,72.545) 30.67,72.545 30.65,72.525 30.65,71.66 30.465,71.475 29.273,71.475 28.3,70.502 28.3,58.746 38.8,48.246 38.8,42.209 42.3,38.709 42.3,37.114 41.536,36.35 41.4,36.35
  Bottom Layer w0.2: C125.1@28.475,53.525 28.65,53.7 v1(29.7,53.7)
  Bottom Layer w0.3: v1(40.1,36.05) U25.K6@39.7,36.45 v1(40.1,36.85) U25.K5@39.7,37.25 v1(40.1,37.65)
AOUTA: C14.2 CN6.6 U5.11 U6.1 | length 29.8
  Top Layer w0.25: U5.11@36.075,92.15 37.025,92.15 37.35,91.825 C14.2@37.95,91.825 37.95,91.85 38.08,91.98 38.6,92.5 40.55,92.5 41.253,93.203 41.253,95.878 41.896,96.521 44.354,96.521 44.725,96.15 44.725,95.07 U6.1@44.55,94.895 ; U6.1@44.725,94.9 v1(45.492,94.9)
  Bottom Layer w0.25: v1(45.492,94.9) 46.892,96.3 59.475,96.3 CN6.6@59.975,96.8
AOUTB: C15.2 CN6.4 U5.10 U6.6 | length 30.3
  Top Layer w0.25: U5.10@36.075,91.65 36.084,91.641 36.534,91.641 37.53,90.645 37.82,90.645 37.95,90.515 C15.2@37.95,90.5 38.08,90.63 38.08,90.705 38.525,91.15 41.1,91.15 41.4,91.45 42.975,91.45 43.3,91.125 44.275,91.125 44.725,91.575 U6.6@44.725,92.6 44.8,92.525 v1(45.61,92.525)
  Bottom Layer w0.25: v1(45.61,92.525) 44.825,93.31 44.825,95.121 46.604,96.9 51.875,96.9 53.075,98.1 CN6.4@53.075,104.2
Audio_MEMs_LED: R1.2 R2.1 U4.7 U25.M9 | length 156.7
  Top Layer w0.12: U4.7@41.45,103.825 42.025,103.825 42.6,103.25 R2.1@42.6,102.125 ; R1.2@41.8,102.125 R2.1@42.6,102.125 ; v1(54.3,32.175) 55.2,31.275 64.349,31.275 65.14,30.484 65.14,29.469 65.986,28.622 v1(79.953,28.622) ; v1(76.149,103.049) v1(76.149,103.049) v1(76.149,103.049) 51.5,103.05 49.45,101 43.1,101 42.6,101.5 R2.1@42.6,102.125
  Signal Layer 3 w0.12: v3(41.475,33.875) 46.6,33.875 52.225,33.875 53.925,32.175 v1(54.3,32.175) ; v1(76.149,103.049) 76.15,57.85 77.05,56.95 77.05,40.775 79.953,37.872 v1(79.953,28.622)
  Signal Layer 4 w0.1: v3(41.475,33.875) v2(41.7,33.65)
  Bottom Layer w0.12: U25.M9@41.3,34.05 v2(41.7,33.65)
Audio_RSTn: R5.2 U5.25 U25.D11 | length 133.7
  Top Layer w0.12: v1(29.925,97.4) R5.2@30.675,97.4 30.675,96.425 31.225,95.875 U5.25@31.225,94.65
  Signal Layer 3 w0.1: v3(31.3,22.95) 31.3,25.192 32.203,26.095 32.203,31.392 33.086,32.275 v3(34.725,32.275)
  Signal Layer 3 w0.12: v1(14.925,92.025) 14.925,54.428 11.44,50.943 11.44,46.882 14.368,43.954 14.368,42.188 14.67,41.886 14.67,41.175 14.835,41.01 14.835,40.585 12.7,38.45 12.7,21.75 13.51,20.94 16.34,20.94 16.95,21.55 23.45,21.55 25.12,19.88 25.12,18.08 v1(25.6,17.6)
  Signal Layer 4 w0.1: v2(31.075,22.725) v3(31.3,22.95) ; v2(34.5,32.05) v3(34.725,32.275)
  Bottom Layer w0.1: 27.425,17.6 29.4,17.6 30.275,18.475 30.275,21.925 v2(31.075,22.725)
  Bottom Layer w0.12: v1(14.925,92.025) 17.325,92.025 22.7,97.4 v1(29.925,97.4) ; v1(25.6,17.6) 27.425,17.6 ; v2(34.5,32.05) U25.D11@34.9,32.45
AVDD_TOF_SENSOR: C21.2 SB12.2 SB13.2 SB60.2 U7.B1 U7.B7 | length 8.4
  Top Layer w0.5: U7.B7@4.875,89.25 5.325,89.7 v1(5.555,89.7)
  Top Layer w0.7: 6,81.375 SB13.2@6.2,81.375 ; 6.225,80.275 SB13.2@6.225,81.375
  Signal Layer 2 w0.75: v1(5.555,89.7) 5.636,89.618 v1(5.636,83.5)
BLGND: C119.2 C120.1 CN2.27 CN2.29 L5.2 | length 8.8
  Top Layer w0.3: 50.385,82.738 CN2.29@50.385,84.097 ; 50.885,82.738 CN2.27@50.885,84.097
  Top Layer w0.5: v1@50.385,82.359 v1(50.391,82.353) 50.5,82.353 50.885,82.738 50.385,82.738 v1@50.385,82.359
  Bottom Layer w0.5: C119.2@49.425,83.525 49.504,83.446 50.304,83.446 50.945,82.805 50.945,82.426 C120.1@50.95,82.421 50.95,82.396 50.945,82.391 50.43,82.391 v1(50.391,82.353)
  Bottom Layer w0.75: L5.2@49.425,82.296 49.425,83.525 C119.2@49.425,83.996
DBn: R35.2 R41.2 U9.2 U11.10 | length 7.2
  Top Layer w0.12: U11.10@18.975,19.075 18.975,19.3 20.325,20.65 20.325,20.94 20.585,21.2 R35.2@20.725,21.2 ; R35.2@20.725,20.95 U9.2@21.975,20.95 22.85,20.95 23.1,20.7 R41.2@23.1,18.925
DS: R30.2 U26.H5 U27.H5 | length 3.9
  Top Layer w0.09: R30.2@19.7,32.025 v1(20.475,32.025)
  Bottom Layer w0.08: 18.835,31.536 20.361,31.536
  Bottom Layer w0.09: U27.H5@18.085,30.786 18.835,31.536 ; 20.361,31.536 20.475,31.65 v1(20.475,32.025)
DSI.CK_N: CN2.3 U25.J1 | length 66.8
  Top Layer w0.09: CN2.3@56.763,83.15 56.763,82.597 56.762,82.508 56.95,82.32 v1(56.95,82.275)
  Bottom Layer w0.09: U25.J1@38.9,40.45 38.9,40.645 38.675,40.87 38.675,51.22 39.978,52.523 40.14,52.685 40.297,52.842 40.297,53.258 39.747,53.807 39.747,54.016 39.956,54.224 40.164,54.224 40.714,53.675 41.13,53.675 41.485,54.03 41.485,54.446 40.935,54.995 40.935,55.204 41.144,55.412 41.352,55.412 41.902,54.863 42.317,54.863 42.673,55.218 42.673,55.634 42.123,56.183 42.123,56.392 42.332,56.6 42.54,56.6 43.09,56.051 43.505,56.051 43.86,56.406 43.86,56.821 43.311,57.371 43.311,57.58 43.52,57.788 43.728,57.788 44.278,57.239 44.693,57.239 45.048,57.594 45.048,58.009 44.575,58.483 44.575,58.692 44.783,58.9 44.992,58.9 45.466,58.427 45.881,58.427 46.185,58.73 46.288,58.833 46.676,59.221 56.776,59.221 58.055,60.5 58.055,77 57.603,77.452 57.603,80.747 56.762,81.588 56.762,82.042 56.95,82.23 v1(56.95,82.275)
DSI.CK_P: CN2.5 U25.H1 | length 66.9
  Top Layer w0.09: v1(56.325,82.275) 56.325,82.32 56.512,82.508 56.512,82.7 CN2.5@56.513,83.15
  Bottom Layer w0.09: U25.H1@38.1,40.45 38.425,40.775 38.425,51.324 39.801,52.7 39.963,52.862 40.047,52.946 40.047,53.154 39.497,53.704 39.497,54.119 39.852,54.474 40.268,54.474 40.817,53.925 41.026,53.925 41.235,54.133 41.235,54.342 40.685,54.892 40.685,55.307 41.04,55.662 41.456,55.662 42.005,55.113 42.214,55.113 42.423,55.321 42.423,55.53 41.873,56.08 41.873,56.495 42.228,56.85 42.644,56.85 43.193,56.301 43.402,56.301 43.61,56.509 43.61,56.718 43.061,57.267 43.061,57.683 43.416,58.038 43.832,58.038 44.381,57.489 44.59,57.489 44.798,57.697 44.798,57.906 44.325,58.379 44.325,58.795 44.68,59.15 45.095,59.15 45.569,58.677 45.778,58.677 46.008,58.907 46.111,59.01 46.573,59.471 56.673,59.471 57.805,60.604 57.805,76.896 57.353,77.348 57.353,80.643 56.512,81.484 56.512,82.042 56.325,82.23 v1(56.325,82.275)
DSI.D0_N: CN2.11 U25.G2 | length 68.5
  Top Layer w0.09: v1(54.8,82.275) 54.8,82.32 55.014,82.534 55.014,83.137 54.994,83.157 54.994,84.175 CN2.11@54.889,84.28
  Bottom Layer w0.09: U25.G2@37.3,39.65 37.005,39.945 37.005,41.005 37.325,41.325 37.325,51.822 38.367,52.864 38.367,54.283 38.367,54.659 37.749,55.277 37.749,55.693 38.104,56.048 38.52,56.048 39.069,55.498 39.278,55.498 39.486,55.707 39.486,55.915 38.937,56.465 38.937,56.88 39.292,57.236 39.708,57.236 40.257,56.686 40.466,56.686 40.674,56.895 40.674,57.103 40.125,57.653 40.125,58.068 40.48,58.423 40.896,58.423 41.445,57.874 41.654,57.874 41.862,58.083 41.862,58.291 41.313,58.841 41.313,59.256 41.668,59.611 42.083,59.611 42.633,59.062 42.842,59.062 43.525,59.745 44.381,60.601 56.205,60.601 56.675,61.072 56.675,76.428 56.223,76.88 56.223,80.175 54.988,81.411 54.988,82.042 54.8,82.23 v1(54.8,82.275)
DSI.D0_P: CN2.9 U25.G1 | length 67.5
  Top Layer w0.09: CN2.9@55.389,84.28 55.284,84.175 55.284,83.157 55.264,83.137 55.264,82.519 55.425,82.358 v1(55.425,82.275)
  Bottom Layer w0.09: U25.G1@37.3,40.45 37.3,40.946 37.575,41.221 37.575,51.718 38.617,52.761 38.617,54.033 38.617,54.762 37.999,55.38 37.999,55.589 38.208,55.798 38.416,55.798 38.966,55.248 39.381,55.248 39.736,55.603 39.736,56.019 39.187,56.568 39.187,56.777 39.395,56.986 39.604,56.986 40.154,56.436 40.569,56.436 40.924,56.791 40.924,57.207 40.375,57.756 40.375,57.965 40.583,58.173 40.792,58.173 41.342,57.624 41.757,57.624 42.112,57.979 42.112,58.395 41.563,58.944 41.563,59.153 41.771,59.361 41.98,59.361 42.529,58.812 42.945,58.812 43.701,59.568 44.485,60.351 56.308,60.351 56.925,60.968 56.925,76.532 56.686,76.77 56.473,76.984 56.473,80.279 55.238,81.514 55.238,82.042 55.425,82.23 v1(55.425,82.275)
DSI.D1_N: CN2.17 U25.K1 | length 67.5
  Top Layer w0.09: v1(53.35,86.25) 53.35,86.181 53.514,86.017 53.514,85.55 53.514,85.423 53.494,85.403 53.494,84.385 CN2.17@53.389,84.28
  Bottom Layer w0.09: U25.K1@39.7,40.45 39.7,41.325 39.775,41.4 39.775,50.722 47.144,58.091 57.244,58.091 59.185,60.032 59.185,77.468 58.88,77.772 58.733,77.92 58.733,84.896 56.579,87.05 53.834,87.05 53.538,86.754 53.538,86.535 53.35,86.347 v1(53.35,86.25)
DSI.D1_P: CN2.15 U25.K2 | length 68.4
  Top Layer w0.09: CN2.15@53.889,84.28 53.784,84.385 53.784,85.403 53.764,85.423 53.764,85.654 53.764,86.014 53.975,86.225 v1(53.975,86.25)
  Bottom Layer w0.09: U25.K2@39.7,39.65 39.4,39.95 39.4,41.379 39.525,41.504 39.525,50.826 47.041,58.341 57.141,58.341 58.935,60.136 58.935,77.364 58.792,77.507 58.615,77.684 58.483,77.816 58.483,84.792 58.172,85.103 57.96,85.103 57.783,85.28 57.783,85.492 57.606,85.669 57.394,85.669 57.217,85.846 57.217,86.058 57.041,86.234 56.829,86.234 56.652,86.411 56.652,86.623 56.475,86.8 56.338,86.8 56.188,86.65 55.938,86.65 55.788,86.8 55.538,86.8 55.388,86.65 55.138,86.65 54.988,86.8 54.738,86.8 54.588,86.65 54.338,86.65 54.188,86.8 53.938,86.8 53.787,86.65 53.787,86.535 53.975,86.347 v1(53.975,86.25)
DSI_BL_CTRL: CN2.53 U25.D5 | length 61.8
  Top Layer w0.1: v1(33.461,82.814) 33.95,82.325 39.7,82.325 40.225,82.85 41.126,82.85 41.726,82.25 44.05,82.25 44.389,82.589 CN2.53@44.389,84.28
  Signal Layer 3 w0.1: v1(33.461,82.814) 33.461,50.205 33.825,49.841 33.825,45.372 33.253,44.8 33.253,42.772 35.6,40.425 35.6,37.725 35.3,37.425 v3(34.725,37.425)
  Signal Layer 4 w0.1: v2(34.5,37.65) v3(34.725,37.425)
  Bottom Layer w0.12: v2(34.5,37.65) U25.D5@34.9,37.25
DSI_PWR_ON: R73.1 R74.1 R75.1 R76.1 R78.1 U25.C4 | length 108.8
  Top Layer w0.12: v1(18.25,72.575) 18.254,72.579 27.31,72.579 28.834,71.055 34.22,71.055 35.1,70.175 39.265,70.175 42.087,72.996 42.679,72.996 v1(42.7,72.975) v1(42.7,66.55)
  Signal Layer 2 w0.12: v1(42.7,72.975) 44.975,70.7 v1(49.875,70.7) v1(53.575,70.7)
  Signal Layer 3 w0.1: v3(16.325,43.15) 18.45,45.275 18.45,68.5 18.25,68.7 18.25,71.053 v1(18.25,72.575)
  Signal Layer 3 w0.12: v1(53.525,61.975) 53.525,63.119 53.575,63.169 v1(53.575,70.7)
  Signal Layer 4 w0.1: v3(16.325,43.15) v2(16.55,42.925)
  Bottom Layer w0.1: 27.425,41.65 29.575,39.5 31.025,39.5 31.975,38.55 33.6,38.55 U25.C4@34.1,38.05
  Bottom Layer w0.12: v2(16.55,42.925) 16.82,43.195 18.183,43.195 18.263,43.115 23.899,43.115 24.694,42.32 26.755,42.32 27.425,41.65 ; R73.1@41.95,72.996 41.971,72.975 v1(42.7,72.975) ; v1(42.7,66.55) R76.1@42.7,67.346 ; R75.1@49.2,70.696 v1@49.821,70.696 ; R78.1@52.025,62.675 52.22,62.48 52.22,62.252 52.497,61.975 v1(53.525,61.975) ; R74.1@52.9,70.696 v1@53.521,70.696
DSI_RESETn: CN2.57 R71.2 U25.B8 | length 91.2
  Top Layer w0.1: v1(32.3,83.525) 32.6,83.825 41.158,83.825 42.258,82.725 43.1,82.725 43.389,83.014 CN2.57@43.389,84.28
  Signal Layer 3 w0.1: v3(17.05,40.95) 17.05,41.95 16.05,42.95 16.05,43.325 18.229,45.504 18.229,68.121 17.875,68.475 v1(17.875,70.525) ; v1(32.3,73.7) v1(32.3,83.525)
  Signal Layer 4 w0.1: v3(17.05,40.95) v2(17.275,40.725)
  Bottom Layer w0.1: v2(17.275,40.725) 22.895,40.725 24.58,39.04 24.58,37.335 26.245,35.67 31.892,35.67 32.212,35.35 32.8,35.35 U25.B8@33.3,34.85
  Bottom Layer w0.12: v1(17.875,70.525) 17.876,70.524 19.554,70.524 20.199,69.879 20.321,69.879 20.331,69.889 23.769,69.889 23.779,69.879 26.01,69.879 27.75,71.619 R71.2@27.75,73.7 v1(32.3,73.7)
DSI_SPI_USART_CS: SB15.2 U25.N13 | length 71.6
  Top Layer w0.12: SB15.2@53.45,75.496 53.476,75.471 53.604,75.471 54.175,74.9 54.175,70.375 55.075,69.475 v1(61.028,69.475) v1@61.05,69.475
  Signal Layer 3 w0.12: v1(45.625,27.625) 48.35,27.625 49.975,29.25 54.825,29.25 58.625,33.05 58.625,36.925 57.6,37.95 57.6,48.025 61.399,51.824 61.399,69.104 v1(61.028,69.475)
  Bottom Layer w0.1: U25.N13@42.1,30.85 42.3,30.85 42.8,30.35 43.125,30.35 43.4,30.075 43.4,29.85 43.65,29.6 43.8,29.6 44.679,28.721 44.679,28.571 v1(45.625,27.625)
DSI_SWIRE: CN2.43 U25.D4 | length 62.2
  Top Layer w0.1: v1(32.925,81.875) 46.45,81.875 46.889,82.314 CN2.43@46.889,84.28
  Signal Layer 3 w0.1: v1(32.925,81.875) 32.925,41.828 35.35,39.402 35.35,38.4 35.2,38.25 v3(34.7,38.25)
  Signal Layer 4 w0.1: v2(34.475,38.475) v3(34.7,38.25)
  Bottom Layer w0.12: v2(34.475,38.475) U25.D4@34.9,38.05
DSI_TE: CN2.49 U25.P7 | length 56.3
  Top Layer w0.12: v1(45.389,82.464) CN2.49@45.389,84.28
  Signal Layer 3 w0.12: v1(45.389,82.464) 45.389,56.486 46.65,55.225 46.65,44.2 45.1,42.65 45.1,39.625 45.1,38.088 45.698,37.49 46.14,37.49 46.388,37.738 v3(47.763,37.738)
  Signal Layer 4 w0.1: v2(47.763,37.338) v3(47.763,37.738)
  Bottom Layer w0.1: U25.P7@42.9,35.65 43.2,35.95 45.975,35.95 47.11,37.085 47.51,37.085 v2(47.763,37.338)
DSI_TOUCH_INT: CN2.4 R72.1 U25.M8 | length 81.4
  Top Layer w0.12: v1(55.5,71.025) 56.889,72.414 CN2.4@56.889,78.54
  Signal Layer 3 w0.1: v3(41.475,35.025) 44.925,35.025 46.263,36.363 48.055,36.363 48.475,36.784 48.475,37.15 48.275,37.35 46.475,37.35 46.35,37.225 45.175,37.225 44.1,38.3 44.1,40.1 44.5,40.5 44.5,53.8 43.4,54.9 43.4,63.6 v1@44.7,64.9
  Signal Layer 4 w0.1: v3(41.475,35.025) v2(41.7,35.25)
  Bottom Layer w0.1: v1(44.788,64.9) 45.425,64.9 47.425,66.9 47.425,71.396 47.95,71.921 R72.1@47.95,72.471
  Bottom Layer w0.12: U25.M8@41.3,34.85 v2(41.7,35.25) ; v1(44.788,64.9) 44.788,63.487 46.775,61.5 55.225,61.5 55.5,61.775 v1(55.5,71.025)
eMMC.RSTn: R111.2 R112.1 U26.K5 U27.K5 | length 10
  Bottom Layer w0.08: 18.929,29.536 20.299,29.536
  Bottom Layer w0.1: U27.K5@18.085,29.786 18.689,29.786 18.929,29.546 ; R112.1@19.2,23.5 R111.2@20.275,23.5 20.475,23.7 20.575,23.7 20.925,24.05 20.925,28.92 20.299,29.546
